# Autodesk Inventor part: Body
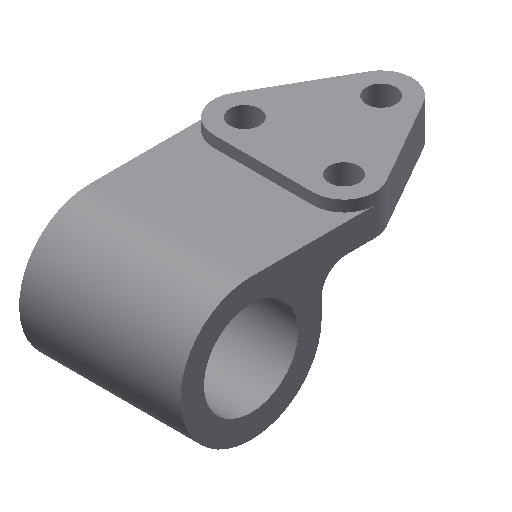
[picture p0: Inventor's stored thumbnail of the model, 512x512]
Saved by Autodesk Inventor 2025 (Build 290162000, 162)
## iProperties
Created: 2010-03
Part Number: Body
Document SubType Name: Modeling
Designer: bhakira
Density: 1 g/cm^3
Material: Generic
Appearance: Default
Author: bhakira
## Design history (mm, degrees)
sketch "Sketch1"
  geometry: L1 (10.853, 41.202)-(30.853, 6.202); L2 (-10.853, 41.202)-(-30.853, 6.202); L3 (-20, -12.5)-(20, -12.5); C1 r 6 at (0, 35); A1 r 12.5 centre (0, 35) between (10.853, 41.202) and (-10.853, 41.202); A2 r 12.5 centre (-20, 0) between (-30.853, 6.202) and (-20, -12.5); A3 r 12.5 centre (20, 0) between (20, -12.5) and (30.853, 6.202); 1 further point
  constraints: 6 end point, 6 point on circle, 6 tangent, 4 centre point, 3 horizontal alignment, 2 equal radius, 1 coincident, 1 vertical alignment, 1 other
  dimensions: "d25" = 35 vertical distance of A1.centre A2.centre; "d27" = 12.5 radius of A1; "d28" = 40 distance of A3.centre A2.centre; "d29" = 20 horizontal distance of A3.centre A1.centre
extrude "Extrusion1" new body sketch "Sketch1" distance "d6" = 16; taper "d7" = 0 deg
workplane "Work Plane2"
workplane "Work Plane3"
sketch "Sketch2"
  geometry: L1 (0, 11.5)-(0, 0); L2 (-12.5, 16)-(6.202, 16) reference; L3 (-50, 11.5)-(0, 11.5); L4 (0, 0)-(-21.5, 0); L5 (-21.5, -17)-(-21.5, 0); L6 (-12.5, 0)-(-12.5, 16) reference; C1 r 19 at (-50, -17); A1 r 28.5 centre (-50, -17) between (-50, 11.5) and (-21.5, -17)
  constraints: 8 end point, 2 centre point, 2 horizontal, 2 point on circle, 2 tangent, 1 coincident, 1 perpendicular, 1 vertical
  dimensions: "d9" = 38 diameter of C1; "d10" = 57 diameter of A1; "d11" = 50 distance from line of L1 C1.centre; "d12" = 33 distance from line of C1.centre L2
extrude "Extrusion2" join sketch "Sketch2" stored distance "d14" = 63.5; taper "d15" = 0 deg
sketch "Sketch3"
  geometry: C1 r 6 at (20, 0) reference; C2 r 6 at (-20, 0) reference; C3 r 6 at (0, 35); 1 further point
  constraints: 1 centre point
extrude "Extrusion3" cut sketch "Sketch3" distance "d16" = 63.5; taper "d17" = 0 deg
hole "Hole1" diameter "d32" = 12; stored, may be unused: countersink angle "d36" = 90 deg, drill point angle "d38" = 118 deg; dims "d33" = 6, "d34" = 4, "d35" = 2082.8, "d37" = 8, "d39" = 10, "d40" = 10
fillet "Fillet1" dims "d42" = 10
body "Solid1"
node "Sketch4"
